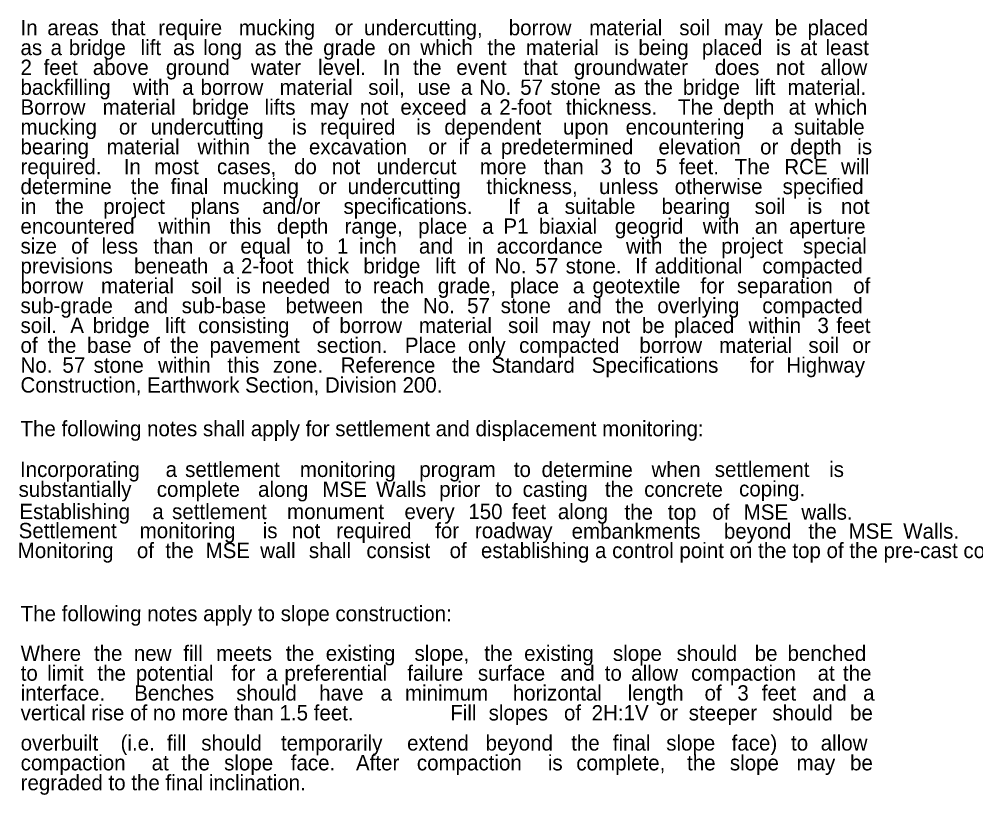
# Model space of a CAD drawing. Extents: x 4804 to 5434, y 4929 to 5221.
# Drawn here: x 4804.1 to 4890.5, y 4928.9 to 4998.9 of the extents above; entities that cross this region are included whole.
import ezdxf

# ---------------------------------------------------------------- set-up
doc = ezdxf.new("R2010")
doc.units = 0
doc.layers.add('RD_TX_RoadID', color=7, linetype='Continuous')

msp = doc.modelspace()

# ---------------------------------------------------------------- texts
at = {"layer": 'RD_TX_RoadID'}
for s, p in [('In ', (4804.251, 4997.452)), ('that ', (4812.436, 4997.452)), ('require ', (4816.687, 4997.452)), ('mucking ', (4823.95, 4997.452)), ('undercutting, ', (4835.25, 4997.452)), ('borrow ', (4848.313, 4997.452)), ('material ', (4855.574, 4997.452)), ('soil ', (4863.697, 4997.452)), ('be ', (4872.312, 4997.452)), ('placed ', (4875.275, 4997.452)), ('areas ', (4806.676, 4997.452)), ('or ', (4832.61, 4997.452)), ('may ', (4867.735, 4997.452)), ('bridge ', (4808.611, 4995.66)), ('lift ', (4815.088, 4995.66)), ('long ', (4820.734, 4995.66)), ('the ', (4828.101, 4995.66)), ('grade ', (4831.569, 4995.66)), ('which ', (4840.334, 4995.66)), ('the ', (4846.382, 4995.66)), ('material ', (4849.849, 4995.66)), ('is ', (4857.833, 4995.66)), ('being ', (4860.012, 4995.66)), ('placed ', (4865.737, 4995.66)), ('is ', (4872.431, 4995.66)), ('at ', (4874.61, 4995.66)), ('least ', (4876.896, 4995.66)), ('as ', (4804.251, 4995.66)), ('a ', (4806.968, 4995.66)), ('as ', (4818.017, 4995.66)), ('as ', (4825.384, 4995.66)), ('on ', (4837.403, 4995.66)), ('2 ', (4804.251, 4993.868)), ('feet ', (4806.333, 4993.868)), ('above ', (4810.778, 4993.868)), ('ground ', (4817.374, 4993.868)), ('level. ', (4831.101, 4993.868)), ('In ', (4836.945, 4993.868)), ('the ', (4839.671, 4993.868)), ('that ', (4849.637, 4993.868)), ('groundwater ', (4854.189, 4993.868)), ('does ', (4866.909, 4993.868)), ('allow ', (4876.444, 4993.868)), ('water ', (4825.043, 4993.868)), ('event ', (4843.579, 4993.868)), ('not ', (4872.43, 4993.868)), ('backfilling ', (4804.251, 4992.076)), ('with ', (4814.395, 4992.076)), ('borrow ', (4820.499, 4992.076)), ('material ', (4827.634, 4992.076)), ('soil, ', (4835.631, 4992.076)), ('the ', (4860.545, 4992.076)), ('bridge ', (4864.026, 4992.076)), ('lift ', (4870.517, 4992.076)), ('material. ', (4873.459, 4992.076)), ('a ', (4818.843, 4992.076)), ('use ', (4840.08, 4992.076)), ('a ', (4843.993, 4992.076)), ('No. ', (4845.648, 4992.076)), ('57 ', (4849.345, 4992.076)), ('stone ', (4852.076, 4992.076)), ('as ', (4857.814, 4992.076)), ('Borrow ', (4804.251, 4990.284)), ('material ', (4811.666, 4990.284)), ('bridge ', (4819.727, 4990.284)), ('lifts ', (4826.282, 4990.284)), ('may ', (4830.364, 4990.284)), ('not ', (4834.879, 4990.284)), ('exceed ', (4838.532, 4990.284)), ('a ', (4845.735, 4990.284)), ('2-foot ', (4847.455, 4990.284)), ('thickness. ', (4853.47, 4990.284)), ('The ', (4863.573, 4990.284)), ('depth ', (4867.656, 4990.284)), ('at ', (4873.566, 4990.284)), ('which ', (4875.929, 4990.284)), ('mucking ', (4804.251, 4988.493)), ('or ', (4813.133, 4988.493)), ('undercutting ', (4815.997, 4988.493)), ('is ', (4828.745, 4988.493)), ('required ', (4831.286, 4988.493)), ('is ', (4839.953, 4988.493)), ('dependent ', (4842.495, 4988.493)), ('upon ', (4853.203, 4988.493)), ('encountering ', (4858.86, 4988.493)), ('a ', (4872.039, 4988.493)), ('suitable ', (4874.044, 4988.493)), ('bearing ', (4804.251, 4986.701)), ('material ', (4812.022, 4986.701)), ('within ', (4820.223, 4986.701)), ('the ', (4826.594, 4986.701)), ('excavation ', (4830.28, 4986.701)), ('or ', (4841.061, 4986.701)), ('if ', (4843.78, 4986.701)), ('a ', (4845.745, 4986.701)), ('predetermined ', (4847.606, 4986.701)), ('elevation ', (4861.825, 4986.701)), ('or ', (4870.992, 4986.701)), ('depth ', (4873.712, 4986.701)), ('is ', (4879.761, 4986.701)), ('required. ', (4804.251, 4984.909)), ('In ', (4813.565, 4984.909)), ('most ', (4816.323, 4984.909)), ('cases, ', (4821.983, 4984.909)), ('do ', (4828.935, 4984.909)), ('not ', (4832.338, 4984.909)), ('undercut ', (4836.384, 4984.909)), ('more ', (4845.697, 4984.909)), ('than ', (4851.466, 4984.909)), ('3 ', (4856.587, 4984.909)), ('to ', (4858.701, 4984.909)), ('5 ', (4861.566, 4984.909)), ('feet. ', (4863.68, 4984.909)), ('The ', (4868.694, 4984.909)), ('RCE ', (4873.172, 4984.909)), ('will ', (4878.295, 4984.909)), ('determine ', (4804.251, 4983.117)), ('the ', (4814.197, 4983.117)), ('final ', (4817.801, 4983.117)), ('mucking ', (4822.48, 4983.117)), ('or ', (4831.137, 4983.117)), ('undercutting ', (4833.774, 4983.117)), ('thickness, ', (4846.296, 4983.117)), ('unless ', (4856.458, 4983.117)), ('otherwise ', (4863.288, 4983.117)), ('specified ', (4873.019, 4983.117)), ('in ', (4804.251, 4981.325)), ('the ', (4807.394, 4981.325)), ('project ', (4811.719, 4981.325)), ('plans ', (4819.59, 4981.325)), ('and/or ', (4826.066, 4981.325)), ('specifications. ', (4833.4, 4981.325)), ('If ', (4848.258, 4981.325)), ('a ', (4850.863, 4981.325)), ('suitable ', (4853.362, 4981.325)), ('bearing ', (4862.094, 4981.325)), ('soil ', (4870.503, 4981.325)), ('is ', (4875.259, 4981.325)), ('not ', (4878.295, 4981.325)), ('encountered ', (4804.251, 4979.533)), ('within ', (4816.694, 4979.533)), ('this ', (4823.118, 4979.533)), ('depth ', (4827.392, 4979.533)), ('range, ', (4833.494, 4979.533)), ('place ', (4840.134, 4979.533)), ('a ', (4845.916, 4979.533)), ('P1 ', (4847.828, 4979.533)), ('biaxial ', (4851.03, 4979.533)), ('geogrid ', (4857.886, 4979.533)), ('with ', (4865.815, 4979.533)), ('an ', (4870.519, 4979.533)), ('aperture ', (4873.613, 4979.533)), ('size ', (4804.251, 4977.742)), ('of ', (4808.823, 4977.742)), ('less ', (4811.566, 4977.742)), ('than ', (4816.245, 4977.742)), ('or ', (4821.245, 4977.742)), ('equal ', (4824.096, 4977.742)), ('to ', (4830.064, 4977.742)), ('1 ', (4832.807, 4977.742)), ('inch ', (4834.799, 4977.742)), (' and ', (4839.692, 4977.742)), ('in ', (4844.585, 4977.742)), ('accordance ', (4847.221, 4977.742)), ('with ', (4858.888, 4977.742)), ('the ', (4863.672, 4977.742)), ('project ', (4867.49, 4977.742)), ('special ', (4874.854, 4977.742)), ('previsions ', (4804.251, 4975.95)), ('beneath ', (4814.503, 4975.95)), ('2-foot ', (4824.15, 4975.95)), ('thick ', (4830.099, 4975.95)), ('bridge ', (4835.19, 4975.95)), ('lift ', (4841.679, 4975.95)), ('of ', (4844.619, 4975.95)), ('No. ', (4847.023, 4975.95)), ('57 ', (4850.718, 4975.95)), ('stone. ', (4853.447, 4975.95)), ('If ', (4859.72, 4975.95)), ('additional ', (4861.48, 4975.95)), ('compacted ', (4871.191, 4975.95)), ('a ', (4822.497, 4975.95)), ('borrow ', (4804.251, 4974.158)), ('material ', (4811.519, 4974.158)), ('soil ', (4819.648, 4974.158)), ('is ', (4823.692, 4974.158)), ('needed ', (4826.017, 4974.158)), ('to ', (4833.501, 4974.158)), ('reach ', (4836.039, 4974.158)), ('grade, ', (4841.912, 4974.158)), ('place ', (4848.428, 4974.158)), ('geotextile ', (4855.873, 4974.158)), ('for ', (4865.613, 4974.158)), ('separation ', (4868.903, 4974.158)), ('of ', (4879.396, 4974.158)), ('a ', (4854.086, 4974.158)), ('sub-grade ', (4804.251, 4972.366)), ('and ', (4814.479, 4972.366)), ('sub-base ', (4818.796, 4972.366)), ('between ', (4828.164, 4972.366)), ('the ', (4836.781, 4972.366)), ('No. ', (4840.56, 4972.366)), ('57 ', (4844.554, 4972.366)), ('stone ', (4847.583, 4972.366)), ('and ', (4853.619, 4972.366)), ('the ', (4857.936, 4972.366)), ('overlying ', (4861.715, 4972.366)), ('compacted ', (4871.191, 4972.366)), ('soil. ', (4804.251, 4970.574)), ('A ', (4808.743, 4970.574)), ('bridge ', (4810.764, 4970.574)), ('lift ', (4817.298, 4970.574)), ('consisting ', (4820.283, 4970.574)), ('of ', (4830.578, 4970.574)), ('borrow ', (4833.027, 4970.574)), ('material ', (4840.205, 4970.574)), ('soil ', (4848.245, 4970.574)), ('be ', (4860.325, 4970.574)), ('placed ', (4863.206, 4970.574)), ('within ', (4869.956, 4970.574)), ('3 ', (4876.166, 4970.574)), ('feet ', (4877.865, 4970.574)), ('may ', (4852.2, 4970.574)), ('not ', (4856.694, 4970.574)), ('of ', (4804.251, 4968.782)), ('the ', (4806.717, 4968.782)), ('base ', (4810.259, 4968.782)), ('of ', (4815.307, 4968.782)), ('the ', (4817.774, 4968.782)), ('section. ', (4830.985, 4968.782)), ('Place ', (4838.933, 4968.782)), ('only ', (4844.627, 4968.782)), ('compacted ', (4849.244, 4968.782)), ('borrow ', (4860.096, 4968.782)), ('material ', (4867.292, 4968.782)), ('soil ', (4875.349, 4968.782)), ('pavement ', (4821.315, 4968.782)), ('or ', (4879.321, 4968.782)), ('within ', (4816.67, 4966.991)), ('this ', (4822.922, 4966.991)), (' Reference ', (4832.633, 4966.991)), ('the ', (4843.187, 4966.991)), ('Standard ', (4846.753, 4966.991)), ('Specifications ', (4855.8, 4966.991)), (' for ', (4869.577, 4966.991)), ('Highway ', (4873.357, 4966.991)), ('No. ', (4804.251, 4966.991)), ('57 ', (4808.032, 4966.991)), ('stone ', (4810.847, 4966.991)), ('zone. ', (4827.024, 4966.991)), ('Construction, Earthwork Section, Division 200. ', (4804.251, 4965.199)), ('The following notes shall apply for settlement and displacement monitoring:', (4804.251, 4961.26)), ('Incorporating ', (4804.206, 4957.581)), ('settlement ', (4819.107, 4957.581)), ('monitoring ', (4829.459, 4957.581)), ('determine ', (4851.272, 4957.581)), ('when ', (4861.195, 4957.581)), ('settlement ', (4866.9, 4957.583)), ('is ', (4877.22, 4957.583)), ('a ', (4817.351, 4957.581)), ('program ', (4840.239, 4957.581)), ('to ', (4848.766, 4957.581)), ('substantially ', (4804.077, 4955.789)), ('complete ', (4816.547, 4955.789)), ('along ', (4825.687, 4955.789)), ('Walls ', (4836.336, 4955.789)), ('prior ', (4842.035, 4955.789)), ('casting ', (4849.565, 4955.789)), ('the ', (4856.984, 4955.789)), ('coping. ', (4869.094, 4955.828)), ('MSE ', (4831.494, 4955.789)), ('to ', (4847.09, 4955.789)), ('concrete ', (4860.534, 4955.789)), ('Establishing ', (4804.151, 4953.775)), ('a ', (4816.143, 4953.775)), ('settlement ', (4817.927, 4953.775)), ('monument ', (4828.306, 4953.775)), ('every ', (4838.901, 4953.775)), ('150 ', (4844.662, 4953.775)), ('feet ', (4848.596, 4953.775)), ('along ', (4852.742, 4953.775)), ('the ', (4858.756, 4953.726)), ('top ', (4862.664, 4953.726)), ('of ', (4866.679, 4953.726)), ('MSE ', (4869.511, 4953.726)), ('walls. ', (4874.711, 4953.726)), (' Settlement ', (4803.572, 4952.051)), ('monitoring ', (4815.003, 4952.051)), ('is ', (4826.109, 4952.051)), ('not ', (4828.729, 4952.051)), ('required', (4832.743, 4952.051)), ('for ', (4841.673, 4952.051)), ('roadway ', (4845.258, 4952.051)), ('embankments ', (4853.983, 4952.007)), ('beyond ', (4867.725, 4952.007)), ('the ', (4875.34, 4952.007)), ('MSE ', (4878.977, 4952.007)), ('Walls. ', (4883.906, 4952.007)), (' Monitoring ', (4803.489, 4950.26)), ('of ', (4814.754, 4950.26)), ('the ', (4817.316, 4950.26)), ('MSE ', (4820.953, 4950.26)), ('wall ', (4825.882, 4950.26)), ('shall', (4830.272, 4950.26)), ('consist ', (4835.466, 4950.26)), ('of ', (4842.973, 4950.26)), ('establishing a control point on the top of the pre-cast concrete panel. ', (4845.802, 4950.261)), ('The following notes apply to slope construction:', (4804.266, 4944.566)), ('Where ', (4804.266, 4940.982)), ('the ', (4810.879, 4940.982)), ('new ', (4814.481, 4940.982)), ('fill ', (4818.945, 4940.982)), ('meets ', (4821.902, 4940.982)), ('the ', (4828.194, 4940.982)), ('existing ', (4831.797, 4940.982)), ('slope, ', (4839.806, 4940.982)), ('the ', (4846.097, 4940.982)), ('existing ', (4849.7, 4940.982)), ('slope ', (4857.709, 4940.982)), ('should ', (4863.463, 4940.982)), ('be ', (4870.505, 4940.982)), ('benched ', (4873.464, 4940.982)), ('to ', (4804.266, 4939.191)), ('limit ', (4806.656, 4939.191)), ('the ', (4811.195, 4939.191)), ('potential ', (4814.66, 4939.191)), ('for ', (4823.283, 4939.191)), ('a ', (4826.425, 4939.191)), ('preferential ', (4828.064, 4939.191)), ('failure ', (4839.16, 4939.191)), ('surface ', (4845.527, 4939.191)), ('and ', (4852.97, 4939.191)), ('to ', (4856.974, 4939.191)), ('allow ', (4859.363, 4939.191)), ('compaction ', (4864.764, 4939.191)), ('at ', (4876.182, 4939.191)), ('the ', (4878.466, 4939.191)), ('interface. ', (4804.266, 4937.399)), (' Benches ', (4813.995, 4937.399)), ('should ', (4823.726, 4937.399)), ('have ', (4831.198, 4937.399)), ('a ', (4836.737, 4937.399)), ('minimum ', (4838.944, 4937.399)), ('horizontal ', (4848.674, 4937.399)), ('length ', (4859.047, 4937.399)), ('of ', (4865.98, 4937.399)), ('3 ', (4868.937, 4937.399)), ('feet ', (4871.144, 4937.399)), ('and ', (4875.714, 4937.399)), ('a ', (4880.285, 4937.399)), ('vertical rise of no more than 1.5 feet.', (4804.266, 4935.607)), ('Fill ', (4843.032, 4935.607)), ('slopes ', (4846.496, 4935.607)), ('of ', (4853.294, 4935.607)), ('2H:1V ', (4855.79, 4935.607)), ('or ', (4861.943, 4935.607)), ('steeper ', (4864.548, 4935.607)), ('should ', (4872.098, 4935.607)), ('be ', (4879.109, 4935.607)), ('overbuilt ', (4804.266, 4932.889)), ('(i.e. ', (4813.282, 4932.889)), ('fill ', (4817.462, 4932.889)), ('should ', (4820.566, 4932.889)), ('temporarily ', (4827.755, 4932.889)), ('extend ', (4839.137, 4932.889)), ('beyond ', (4846.22, 4932.889)), ('the ', (4853.947, 4932.889)), ('final ', (4857.697, 4932.889)), ('slope ', (4862.521, 4932.889)), ('face) ', (4868.422, 4932.889)), ('to ', (4873.785, 4932.889)), ('allow ', (4876.46, 4932.889)), ('compaction ', (4804.266, 4931.097)), ('at ', (4816.083, 4931.097)), ('the ', (4818.764, 4931.097)), ('slope ', (4822.626, 4931.097)), ('face. ', (4828.64, 4931.097)), (' After ', (4834.009, 4931.097)), ('compaction ', (4840.02, 4931.097)), ('is ', (4851.836, 4931.097)), ('complete, ', (4854.411, 4931.097)), ('the ', (4864.4, 4931.097)), ('slope ', (4868.263, 4931.097)), ('may ', (4874.277, 4931.097)), ('be ', (4879.109, 4931.097)), ('regraded to the final inclination.', (4804.266, 4929.306))]:
    msp.add_text(s, height=1.3845, dxfattribs=at).set_placement(p)

doc.saveas('drawing.dxf')
